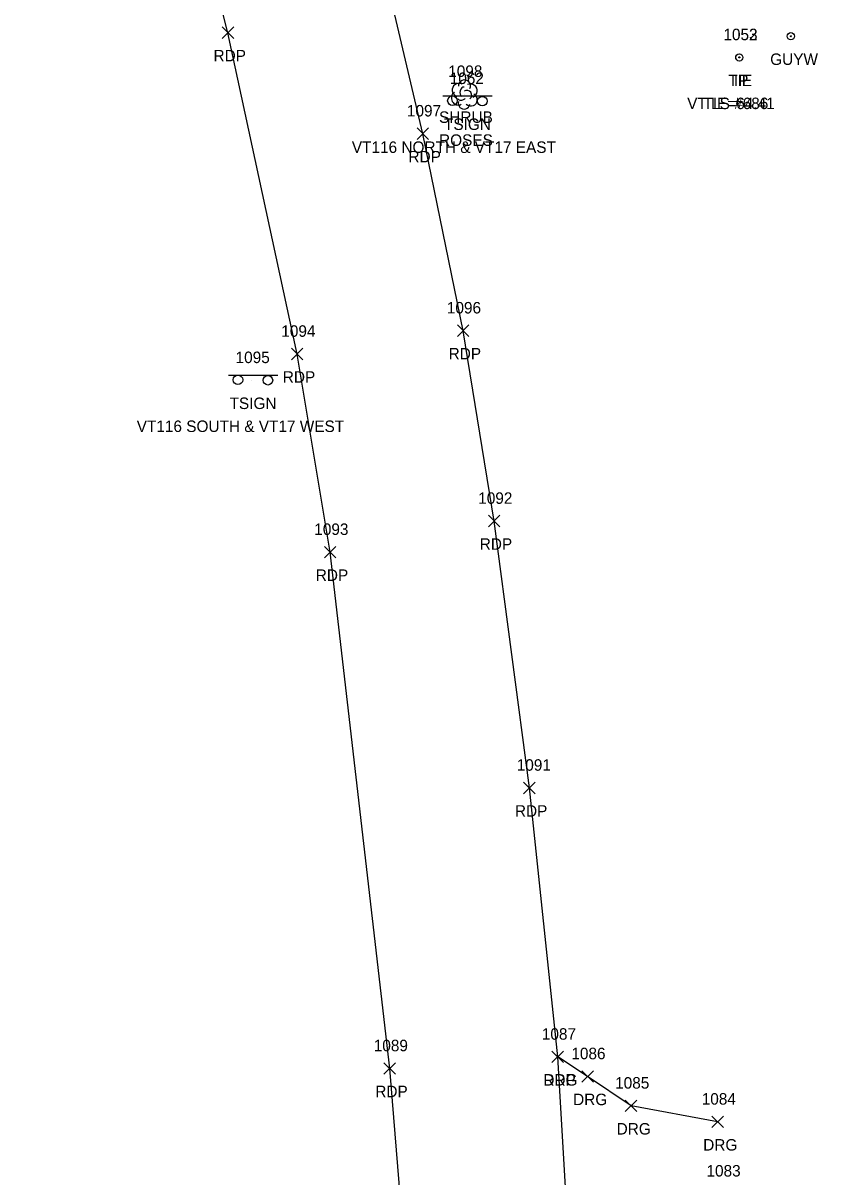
# Model space of a CAD drawing. Extents: x 1496556 to 1498241, y 599216 to 604470.
# Drawn here: x 1497213.5 to 1497351.9, y 602725.1 to 602926.1 of the extents above; entities that cross this region are included whole.
import ezdxf

# ---------------------------------------------------------------- set-up
doc = ezdxf.new("R2010")
doc.units = 0
for name, color, linetype in [('C_A', 7, 'Continuous'), ('C_C', 7, 'Continuous'), ('C_I', 7, 'Continuous'), ('CBP', 7, 'Continuous'), ('L_A', 7, 'Continuous'), ('L_C', 7, 'Continuous'), ('L_I', 7, 'Continuous'), ('LSH', 7, 'Continuous'), ('M_A', 7, 'Continuous'), ('M_C', 7, 'Continuous'), ('M_I', 7, 'Continuous'), ('MPIR', 7, 'Continuous'), ('P_A', 7, 'Continuous'), ('P_I', 7, 'Continuous'), ('P_TIC', 7, 'Continuous'), ('PET', 7, 'Continuous'), ('R_A', 7, 'Continuous'), ('R_I', 7, 'Continuous'), ('R_TIC', 7, 'Continuous'), ('RDG', 7, 'Continuous'), ('S_A', 7, 'Continuous'), ('S_C', 7, 'Continuous'), ('S_I', 7, 'Continuous'), ('SSGN', 7, 'Continuous'), ('U_A', 7, 'Continuous'), ('UPGW', 7, 'Continuous')]:
    doc.layers.add(name, color=color, linetype=linetype)

msp = doc.modelspace()

# ---------------------------------------------------------------- linework, layer by layer
at = {"layer": 'CBP'}
for radius in [0.625, 0.0833]:
    msp.add_circle((1497338.2, 602920.09), radius, dxfattribs=at)
at = {"layer": 'LSH'}
msp.add_line((1497290.31, 602913.69), (1497290.31, 602913.69), dxfattribs=at)
msp.add_line((1497290.31, 602913.69), (1497290.31, 602913.69), dxfattribs=at)
msp.add_arc((1497290.36, 602915.12), 1.05, 335.5272, 180.9563, dxfattribs=at)
for centre, major_axis, ratio, start_param, end_param in [((1497289.52, 602914.35), (1.21, -0.51), 0.895232, 1.570796, 4.712389), ((1497290.11, 602914.14), (-0.208, -0.792), 0.645439, 3.141593, 6.283185), ((1497291.36, 602914.27), (-1.14, -0.48), 0.949671, 1.570796, 4.712389), ((1497289.23, 602912.98), (0.58, -1.04), 0.959034, 3.141593, 6.283185), ((1497289.86, 602912.94), (-0.625, -0.083), 0.423636, 0, 3.141593), ((1497290.81, 602913.52), (-0.5, 0.667), 0.989748, 3.141593, 6.283185), ((1497291.31, 602912.85), (-1.09, 0.79), 0.841452, 1.570796, 4.712389), ((1497290.31, 602912.19), (0.26, 1.06), 0.942809, 1.570796, 4.712389)]:
    msp.add_ellipse(centre, major_axis=major_axis, ratio=ratio, start_param=start_param, end_param=end_param, dxfattribs=at)
at = {"layer": 'MPIR'}
for radius in [0.625, 0.0833]:
    msp.add_circle((1497338.21, 602920.09), radius, dxfattribs=at)
at = {"layer": 'P_TIC'}
for points in [[(1497248.2, 602923.4), (1497250.2, 602925.4)], [(1497250.2, 602923.4), (1497248.2, 602925.4)], [(1497282.12, 602905.81), (1497284.12, 602907.81)], [(1497284.12, 602905.81), (1497282.12, 602907.81)], [(1497289.13, 602871.5), (1497291.13, 602873.5)], [(1497291.13, 602871.5), (1497289.13, 602873.5)], [(1497260.25, 602867.44), (1497262.25, 602869.44)], [(1497262.25, 602867.44), (1497260.25, 602869.44)], [(1497294.53, 602838.35), (1497296.53, 602840.35)], [(1497296.53, 602838.35), (1497294.53, 602840.35)], [(1497265.99, 602832.93), (1497267.99, 602834.93)], [(1497267.99, 602832.93), (1497265.99, 602834.93)], [(1497300.66, 602791.87), (1497302.66, 602793.87)], [(1497302.66, 602791.87), (1497300.66, 602793.87)], [(1497305.6, 602745.03), (1497307.6, 602747.03)], [(1497307.6, 602745.03), (1497305.6, 602747.03)], [(1497276.35, 602743.02), (1497278.35, 602745.02)], [(1497278.35, 602743.02), (1497276.35, 602745.02)]]:
    msp.add_lwpolyline(points, dxfattribs=at)
at = {"layer": 'PET'}
for points in [[(1497255.35, 601840.33), (1497260.72, 601945.51), (1497260.6, 601945.5), (1497265.21, 602060.91), (1497267.76, 602124.12), (1497271.3, 602209.29), (1497274.95, 602307.82), (1497276.81, 602364.31), (1497278.84, 602406.87), (1497280.41, 602449.54), (1497282.45, 602505.14), (1497283.29, 602549.03), (1497283.31, 602599.78), (1497282.4, 602667.07), (1497280.87, 602701.36), (1497277.35, 602744.02), (1497266.99, 602833.93), (1497261.25, 602868.44), (1497249.2, 602924.4), (1497241.75, 602954.09), (1497234.18, 602981.9), (1497224.39, 603014.86), (1497221.77, 603020.8), (1497213.53, 603046.79)], [(1497283.3, 601836.85), (1497288.13, 601944.77), (1497293.47, 602059.45), (1497296.19, 602123.28), (1497299.59, 602207.66), (1497303.16, 602306.06), (1497305.27, 602361.72), (1497306.93, 602406.52), (1497308.5, 602446.65), (1497309.02, 602465.84), (1497310.76, 602505.51), (1497311.54, 602549.49), (1497311.88, 602599.1), (1497311.34, 602649.82), (1497308.95, 602706.57), (1497306.6, 602746.03), (1497301.66, 602792.87), (1497295.53, 602839.35), (1497290.13, 602872.5), (1497283.12, 602906.81), (1497277.08, 602932.51)]]:
    msp.add_lwpolyline(points, dxfattribs=at)
at = {"layer": 'R_TIC'}
for points in [[(1497305.6, 602745.03), (1497307.6, 602747.03)], [(1497307.6, 602745.03), (1497305.6, 602747.03)], [(1497310.8, 602741.63), (1497312.8, 602743.63)], [(1497312.8, 602741.63), (1497310.8, 602743.63)], [(1497318.36, 602736.51), (1497320.36, 602738.51)], [(1497320.36, 602736.51), (1497318.36, 602738.51)], [(1497333.43, 602733.72), (1497335.43, 602735.72)], [(1497335.43, 602733.72), (1497333.43, 602735.72)]]:
    msp.add_lwpolyline(points, dxfattribs=at)
at = {"layer": 'RDG'}
msp.add_lwpolyline([(1497334.43, 602734.72), (1497319.36, 602737.51), (1497311.8, 602742.63), (1497306.6, 602746.03)], dxfattribs=at)
at = {"layer": 'SSGN'}
for p, q in [((1497286.6, 602913.38), (1497295.2, 602913.38)), ((1497290.63, 602912.48), (1497290.63, 602912.48)), ((1497249.27, 602864.78), (1497257.87, 602864.78)), ((1497253.3, 602863.87), (1497253.3, 602863.87))]:
    msp.add_line(p, q, dxfattribs=at)
for centre in [(1497288.27, 602912.55), (1497293.48, 602912.48), (1497250.93, 602863.94), (1497256.15, 602863.87)]:
    msp.add_circle(centre, 0.833, dxfattribs=at)
at = {"layer": 'UPGW'}
for radius in [0.625, 0.0833]:
    msp.add_circle((1497347.18, 602923.78), radius, dxfattribs=at)

# ---------------------------------------------------------------- texts
at = {"layer": 'C_A'}
msp.add_text('TIE', height=2, dxfattribs=at).set_placement((1497336.28, 602915.09))
at = {"layer": 'C_C'}
msp.add_text('TIE=64.41', height=2, dxfattribs=at).set_placement((1497331.95, 602911.09))
at = {"layer": 'C_I'}
msp.add_text('1053', height=2, dxfattribs=at).set_placement((1497335.43, 602923.09))
at = {"layer": 'L_A'}
msp.add_text('SHRUB', height=2, dxfattribs=at).set_placement((1497285.94, 602908.69))
at = {"layer": 'L_C'}
msp.add_text('ROSES', height=2, dxfattribs=at).set_placement((1497285.94, 602904.69))
at = {"layer": 'L_I'}
msp.add_text('1098', height=2, dxfattribs=at).set_placement((1497287.54, 602916.69))
at = {"layer": 'M_A'}
msp.add_text('IP', height=2, dxfattribs=at).set_placement((1497337.26, 602915.09))
at = {"layer": 'M_C'}
msp.add_text('VT LS #686', height=2, dxfattribs=at).set_placement((1497329.13, 602911.09))
at = {"layer": 'M_I'}
msp.add_text('1052', height=2, dxfattribs=at).set_placement((1497335.44, 602923.09))
at = {"layer": 'P_A'}
for p in [(1497246.68, 602919.4), (1497280.61, 602901.81), (1497287.61, 602867.5), (1497258.74, 602863.44), (1497293.02, 602834.35), (1497264.48, 602828.93), (1497299.15, 602787.87), (1497304.09, 602741.03), (1497274.84, 602739.02)]:
    msp.add_text('RDP', height=2, dxfattribs=at).set_placement(p)
at = {"layer": 'P_I'}
for s, p in [('1097', (1497280.35, 602909.81)), ('1096', (1497287.3, 602875.5)), ('1094', (1497258.48, 602871.44)), ('1092', (1497292.76, 602842.35)), ('1093', (1497264.22, 602836.93)), ('1091', (1497299.46, 602795.87)), ('1087', (1497303.83, 602749.03)), ('1089', (1497274.57, 602747.02))]:
    msp.add_text(s, height=2, dxfattribs=at).set_placement(p)
at = {"layer": 'R_A'}
for p in [(1497304.09, 602741.03), (1497309.28, 602737.63), (1497316.85, 602732.51), (1497331.92, 602729.72)]:
    msp.add_text('DRG', height=2, dxfattribs=at).set_placement(p)
at = {"layer": 'R_I'}
for s, p in [('1087', (1497303.83, 602749.03)), ('1086', (1497308.97, 602745.63)), ('1085', (1497316.59, 602740.51)), ('1084', (1497331.66, 602737.72)), ('1083', (1497332.49, 602725.2))]:
    msp.add_text(s, height=2, dxfattribs=at).set_placement(p)
at = {"layer": 'S_A'}
for p in [(1497286.8, 602907.46), (1497249.47, 602858.86)]:
    msp.add_text('TSIGN', height=2, dxfattribs=at).set_placement(p)
at = {"layer": 'S_C'}
for s, p in [('VT116 NORTH & VT17 EAST', (1497270.76, 602903.46)), ('VT116 SOUTH & VT17 WEST', (1497233.31, 602854.86))]:
    msp.add_text(s, height=2, dxfattribs=at).set_placement(p)
at = {"layer": 'S_I'}
for s, p in [('1062', (1497287.8, 602915.46)), ('1095', (1497250.52, 602866.86))]:
    msp.add_text(s, height=2, dxfattribs=at).set_placement(p)
at = {"layer": 'U_A'}
msp.add_text('GUYW', height=2, dxfattribs=at).set_placement((1497343.58, 602918.78))

doc.saveas('drawing.dxf')
